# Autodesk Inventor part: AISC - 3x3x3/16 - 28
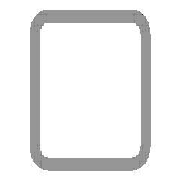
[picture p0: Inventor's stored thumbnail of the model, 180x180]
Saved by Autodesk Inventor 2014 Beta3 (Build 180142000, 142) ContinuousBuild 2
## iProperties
IsCustomPart: 1
Created: 2011-01
Part Number: AISC - 3x3x3/16 - 28
Material: Steel, Mild
Description: Tube
Document SubType Name: Modeling
Standard: ANSI
Designer: Beta-8540w
Standards Organization: ANSI
Language: en-US
Size Designation: 3x3x3/16
Categories: <MemberInstance><Categories><Category DisplayName="Structural Shapes" InternalName="089c4875-fa83-4c05-b084-43b9cc11f5ed" Mnemonic="GRDR"><CategoryParameter Dis
Stock Number: 3x3x3/16
Density: 7.86 g/cm^3
Appearance: Steel
_CCFamilyMember: 9
_CCFamilyDisplayName: ANSI AISC (Square) - Tube
_FrameMemberDoc: Frame Member File
_Version: 15.0.0
_GetPNFromCC: 1
G_L: 28.000 in
G_W: 3.000 in
G_H: 3.000 in
Author: Beta-8540w
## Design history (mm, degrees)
node "Start plane"
node "End plane"
sketch "Sketch"
  geometry: L1 (-38.1, -28.575)-(-38.1, 28.575); L2 (-28.575, 38.1)-(28.575, 38.1); L3 (38.1, 28.575)-(38.1, -28.575); L4 (28.575, -38.1)-(-28.575, -38.1); L5 (-28.575, 33.337)-(28.575, 33.338); L6 (33.338, 28.575)-(33.338, -28.575); L7 (28.575, -33.337)-(-28.575, -33.338); L8 (-33.338, -28.575)-(-33.338, 28.575); L9 (0, 56.102)-(0, -56.102) reference; L10 (-56.102, 0)-(56.102, 0) reference; A1 r 9.525 centre (-28.575, -28.575) between (-38.1, -28.575) and (-28.575, -38.1); A2 r 9.525 centre (-28.575, 28.575) between (-28.575, 38.1) and (-38.1, 28.575); A3 r 9.525 centre (28.575, 28.575) between (38.1, 28.575) and (28.575, 38.1); A4 r 9.525 centre (28.575, -28.575) between (28.575, -38.1) and (38.1, -28.575); A5 r 4.763 centre (-28.575, 28.575) between (-28.575, 33.337) and (-33.338, 28.575); A6 r 4.763 centre (28.575, 28.575) between (33.338, 28.575) and (28.575, 33.338); A7 r 4.763 centre (28.575, -28.575) between (28.575, -33.337) and (33.338, -28.575); A8 r 4.763 centre (-28.575, -28.575) between (-33.338, -28.575) and (-28.575, -33.338)
  constraints: 16 end point, 16 point on circle, 8 centre point, 8 tangent, 4 parallel, 3 equal radius, 2 perpendicular, 7 other
  dimensions: "d10" = 76.2 distance between parallel lines of L2 L4 (= G_H); "d11" = 76.2 distance between parallel lines of L1 L3 (= G_W); "d12" = 4.7625 distance between parallel lines of L3 L6 (= G_T); "d15" = 38.1 distance between parallel lines of L2 L10 (= 0.5 x d10); "d16" = 38.1 distance between parallel lines of L9 L3 (= 0.5 x d11); "d17" = 9.525 radius of A1 (= G_IR)
extrude "Body" new body sketch "Sketch" stored distance "d3" = 711.2 (= G_L); taper "d4" = 0 deg
node "Driven Length"
  sketch "Sketch3"
    geometry: L1 (0, 0)-(10, 0) reference
    constraints: 2 end point, 1 horizontal
  workplane "Work Plane3"
  sketch "Sketch4"
    geometry: L1 (-2, 0)-(12, 0) reference; L2 (-2, 711.2)-(12, 711.2) reference
    dimensions: "d19" = 711.2 distance between parallel lines of L1 L2 (derived)
body "Solid1"
other parameters: "G_W" = 76.2 [user parameter; used in 1 equation term], "G_H" = 76.2 [user parameter; used in 1 equation term], "G_T" = 4.7625 [user parameter; used in 1 equation term], "G_IR" = 9.525 [user parameter; used in 1 equation term], "G_L" = 711.2 (= d19) [user parameter; used in 1 equation term], "G_OFFSET_START" = 0 [user parameter; used in 1 equation term], "G_OFFSET_END" = 0 [user parameter; used in 1 equation term], "d13" = 0 (computed from G_OFFSET_START), "d14" = 711.2 (= G_OFFSET_END + B_L), "B_L" = 711.2 [user parameter; used in 1 equation term], "d18" = 90 deg
